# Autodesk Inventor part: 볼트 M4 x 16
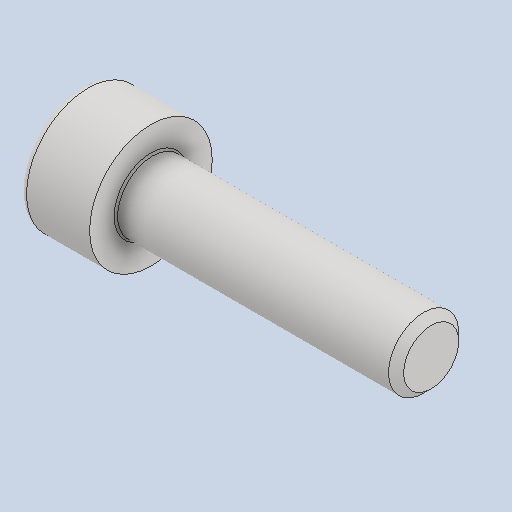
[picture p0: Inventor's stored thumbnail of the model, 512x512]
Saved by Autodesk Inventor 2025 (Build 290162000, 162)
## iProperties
Created: 2025-08
Part Number: 볼트 M4 x 16
Material: 스테인리스강
Description: 6각 소켓 머리 캡 나사
Document SubType Name: Modeling
Designer: infra017
Density: 8.08 g/cm^3
Appearance: 기본값
Author: jhkim
Sending System: Autodesk Inventor 2026
Preprocessor: ST-DEVELOPER v20.1
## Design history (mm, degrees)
feature "Solid1"
node "솔리드1"
